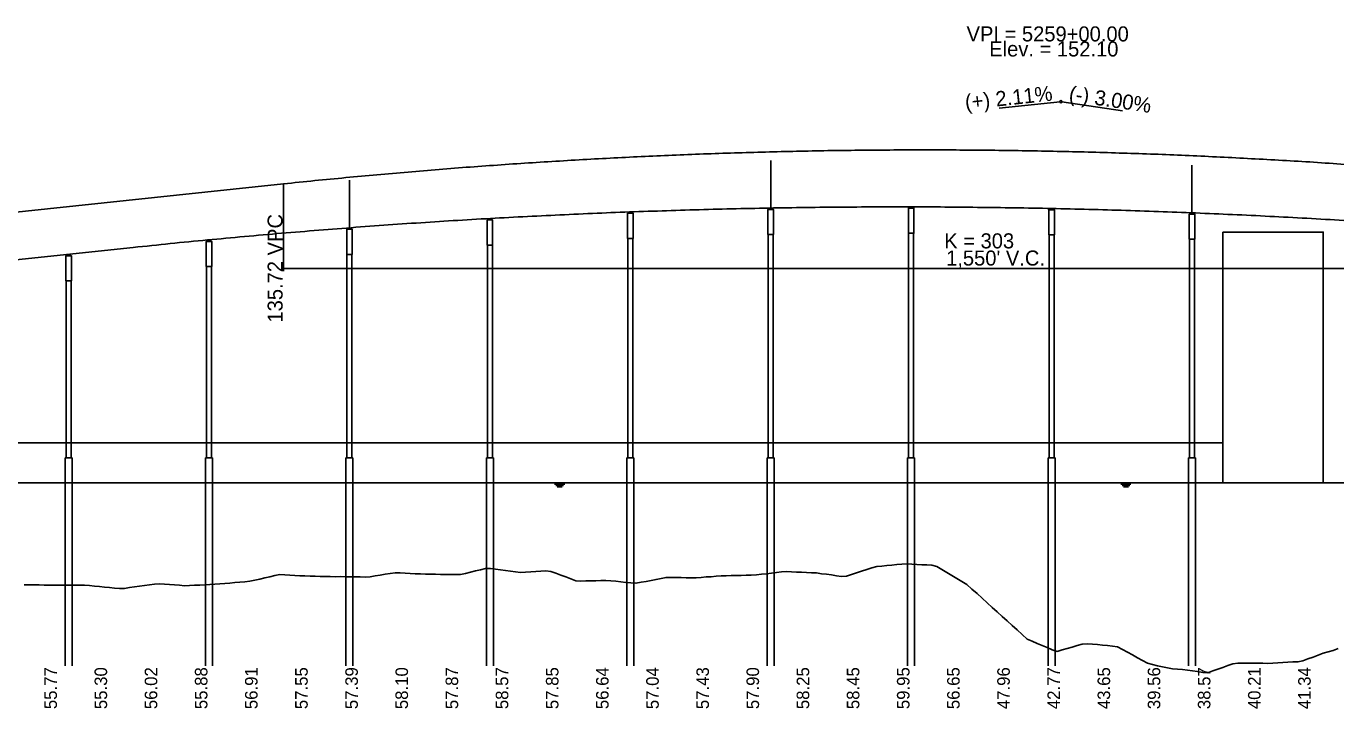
# Model space of a CAD drawing. Extents: x 2121671 to 2169879, y 557274 to 599957.
# Drawn here: x 2154437 to 2155742, y 595763 to 596443 of the extents above; entities that cross this region are included whole.
import ezdxf

# ---------------------------------------------------------------- set-up
doc = ezdxf.new("R2010")
doc.units = 0
for name, color, linetype in [('BR_CONCRETE', 7, 'Continuous'), ('BR_DETAILS', 7, 'Continuous'), ('BR_PRESTRESSED BEAM', 7, 'Continuous'), ('RD_DDB_GradeTX', 7, 'Continuous'), ('RD_DDB_Profile_Elev', 7, 'Continuous'), ('RD_DDB_Profile_EX', 7, 'Continuous'), ('RD_DDB_Profile_Lbl', 7, 'Continuous'), ('RD_DDB_Profile_PR', 7, 'Continuous'), ('RD_DDB_StripGrade', 7, 'Continuous'), ('RD_DDB_VCLbl', 7, 'Continuous')]:
    doc.layers.add(name, color=color, linetype=linetype)

msp = doc.modelspace()

# ---------------------------------------------------------------- linework, layer by layer
at = {"layer": 'BR_CONCRETE'}
for p, q in [((2155176.3, 596235.7), (2155176.3, 596013.1)), ((2155181.3, 596235.7), (2155181.3, 596013.1)), ((2155316.3, 596236.9), (2155316.3, 596013.1)), ((2155321.3, 596236.9), (2155321.3, 596013.1)), ((2155456.3, 596235.3), (2155456.3, 596013.1)), ((2155461.3, 596235.3), (2155461.3, 596013.1)), ((2154896.3, 596225.1), (2154896.3, 596013.1)), ((2154901.3, 596225.1), (2154901.3, 596013.1)), ((2155036.3, 596231.8), (2155036.3, 596013.1)), ((2155041.3, 596231.8), (2155041.3, 596013.1)), ((2155596.3, 596231), (2155596.3, 596013.1)), ((2155601.3, 596231), (2155601.3, 596013.1)), ((2154756.3, 596215.8), (2154756.3, 596013.1)), ((2154761.3, 596215.8), (2154761.3, 596013.1)), ((2154616.3, 596203.8), (2154616.3, 596013.1)), ((2154621.3, 596203.8), (2154621.3, 596013.1)), ((2154476.3, 596189.4), (2154476.3, 596013.1)), ((2154481.3, 596189.4), (2154481.3, 596013.1)), ((2154475.3, 596013.1), (2154475.3, 595805.8)), ((2154482.3, 596013.1), (2154482.3, 595805.8)), ((2154615.3, 596013.1), (2154615.3, 595805.8)), ((2154622.3, 596013.1), (2154622.3, 595805.8)), ((2154755.3, 596013.1), (2154755.3, 595805.8)), ((2154762.3, 596013.1), (2154762.3, 595805.8)), ((2154895.3, 596013.1), (2154895.3, 595805.8)), ((2154902.3, 596013.1), (2154902.3, 595805.8)), ((2155035.3, 596013.1), (2155035.3, 595805.8)), ((2155042.3, 596013.1), (2155042.3, 595805.8)), ((2155175.3, 596013.1), (2155175.3, 595805.8)), ((2155182.3, 596013.1), (2155182.3, 595805.8)), ((2155315.3, 596013.1), (2155315.3, 595805.8)), ((2155322.3, 596013.1), (2155322.3, 595805.8)), ((2155455.3, 596013.1), (2155455.3, 595805.8)), ((2155462.3, 596013.1), (2155462.3, 595805.8)), ((2155595.3, 596013.1), (2155595.3, 595805.8)), ((2155602.3, 596013.1), (2155602.3, 595805.8))]:
    msp.add_line(p, q, dxfattribs=at)
for points in [[(2155176.1, 596235.7), (2155181.6, 596235.7), (2155181.6, 596260.7), (2155176.1, 596260.7)], [(2155316.1, 596236.9), (2155321.6, 596236.9), (2155321.6, 596261.9), (2155316.1, 596261.9)], [(2154896.1, 596225.1), (2154901.6, 596225.1), (2154901.6, 596250.1), (2154896.1, 596250.1)], [(2155036.1, 596231.8), (2155041.6, 596231.8), (2155041.6, 596256.8), (2155036.1, 596256.8)], [(2155456.1, 596235.3), (2155461.6, 596235.3), (2155461.6, 596260.3), (2155456.1, 596260.3)], [(2155596.1, 596231), (2155601.6, 596231), (2155601.6, 596256), (2155596.1, 596256)], [(2154756.1, 596215.8), (2154761.6, 596215.8), (2154761.6, 596240.8), (2154756.1, 596240.8)], [(2154616.1, 596203.8), (2154621.6, 596203.8), (2154621.6, 596228.8), (2154616.1, 596228.8)], [(2154476.1, 596189.4), (2154481.6, 596189.4), (2154481.6, 596214.4), (2154476.1, 596214.4)]]:
    msp.add_lwpolyline(points, close=True, dxfattribs=at)
at = {"layer": 'BR_DETAILS'}
for points in [[(2155177.3, 596261.9), (2155178.3, 596261.9), (2155178.3, 596260.7), (2155177.3, 596260.7)], [(2155179.3, 596261.9), (2155180.3, 596261.9), (2155180.3, 596260.7), (2155179.3, 596260.7)], [(2155317.3, 596263.1), (2155318.3, 596263.1), (2155318.3, 596261.9), (2155317.3, 596261.9)], [(2155319.3, 596263.1), (2155320.3, 596263.1), (2155320.3, 596261.9), (2155319.3, 596261.9)], [(2155457.3, 596261.5), (2155458.3, 596261.5), (2155458.3, 596260.3), (2155457.3, 596260.3)], [(2155459.3, 596261.5), (2155460.3, 596261.5), (2155460.3, 596260.3), (2155459.3, 596260.3)], [(2154897.3, 596251.4), (2154898.3, 596251.4), (2154898.3, 596250.1), (2154897.3, 596250.1)], [(2154899.3, 596251.4), (2154900.3, 596251.4), (2154900.3, 596250.1), (2154899.3, 596250.1)], [(2155037.3, 596258), (2155038.3, 596258), (2155038.3, 596256.8), (2155037.3, 596256.8)], [(2155039.3, 596258), (2155040.3, 596258), (2155040.3, 596256.8), (2155039.3, 596256.8)], [(2155597.3, 596257.3), (2155598.3, 596257.3), (2155598.3, 596256), (2155597.3, 596256)], [(2155599.3, 596257.3), (2155600.3, 596257.3), (2155600.3, 596256), (2155599.3, 596256)], [(2154757.3, 596242.1), (2154758.3, 596242.1), (2154758.3, 596240.8), (2154757.3, 596240.8)], [(2154759.3, 596242.1), (2154760.3, 596242.1), (2154760.3, 596240.8), (2154759.3, 596240.8)], [(2154617.3, 596230), (2154618.3, 596230), (2154618.3, 596228.8), (2154617.3, 596228.8)], [(2154619.3, 596230), (2154620.3, 596230), (2154620.3, 596228.8), (2154619.3, 596228.8)], [(2154477.3, 596215.6), (2154478.3, 596215.6), (2154478.3, 596214.4), (2154477.3, 596214.4)], [(2154479.3, 596215.6), (2154480.3, 596215.6), (2154480.3, 596214.4), (2154479.3, 596214.4)]]:
    msp.add_lwpolyline(points, close=True, dxfattribs=at)
at = {"layer": 'BR_PRESTRESSED BEAM'}
for p, q in [((2155178.8, 596261.9), (2155178.8, 596309.4)), ((2155598.8, 596257.3), (2155598.8, 596304.8)), ((2154758.8, 596242.2), (2154758.8, 596289.7)), ((2154250.2, 596191.8), (2154543.2, 596222.7)), ((2154475.3, 596013.1), (2154482.3, 596013.1)), ((2154615.3, 596013.1), (2154622.3, 596013.1)), ((2154755.3, 596013.1), (2154762.3, 596013.1)), ((2154895.3, 596013.1), (2154902.3, 596013.1)), ((2155035.3, 596013.1), (2155042.3, 596013.1)), ((2155175.3, 596013.1), (2155182.3, 596013.1)), ((2155315.3, 596013.1), (2155322.3, 596013.1)), ((2155455.3, 596013.1), (2155462.3, 596013.1)), ((2155595.3, 596013.1), (2155602.3, 596013.1))]:
    msp.add_line(p, q, dxfattribs=at)
msp.add_spline([(2154543.2, 596222.7), (2154580.2, 596226.6), (2154617.2, 596230.2), (2154654.2, 596233.6), (2154691.2, 596236.9), (2154728.2, 596239.9), (2154765.2, 596242.8), (2154802.2, 596245.5), (2154839.2, 596248), (2154876.2, 596250.3), (2154913.2, 596252.4), (2154950.2, 596254.3), (2154987.2, 596256), (2155024.2, 596257.6), (2155061.2, 596258.9), (2155098.2, 596260.1), (2155135.2, 596261.1), (2155172.2, 596261.9), (2155209.2, 596262.5), (2155246.2, 596262.9), (2155283.2, 596263.1), (2155320.2, 596263.1), (2155357.2, 596263), (2155394.2, 596262.6), (2155431.2, 596262.1), (2155468.2, 596261.3), (2155505.2, 596260.4), (2155542.2, 596259.3), (2155579.2, 596258), (2155616.2, 596256.5), (2155653.2, 596254.9), (2155690.2, 596253), (2155727.2, 596251), (2155764.2, 596248.7), (2155801.2, 596246.3), (2155838.2, 596243.7), (2155875.2, 596240.9), (2155912.2, 596237.9), (2155949.2, 596234.7), (2155986.2, 596231.3), (2156023.2, 596227.7), (2156060.2, 596224), (2156097.2, 596220.1), (2156134.2, 596215.9), (2156171.2, 596211.6), (2156208.2, 596207.1), (2156245.2, 596202.4), (2156282.2, 596197.5), (2156319.2, 596192.4), (2156356.2, 596187.2), (2156393.2, 596181.7)], degree=3, dxfattribs=at)
at = {"layer": 'RD_DDB_GradeTX'}
for p, q in [((2155406.6, 596361.4), (2155467.3, 596367.9)), ((2155529.6, 596358.8), (2155469.2, 596367.8))]:
    msp.add_line(p, q, dxfattribs=at)
msp.add_circle((2155468.2, 596368), 1, dxfattribs=at)
at = {"layer": 'RD_DDB_Profile_Elev'}
for p, q in [((2151940.7, 596028.1), (2155629.7, 596028.1)), ((2151972, 595988.1), (2156334.9, 595988.1)), ((2154963.4, 595986.8), (2154973.4, 595986.8)), ((2155528, 595986.8), (2155538, 595986.8)), ((2154964.7, 595985.6), (2154972.2, 595985.6)), ((2154965.9, 595984.3), (2154970.9, 595984.3)), ((2155529.3, 595985.6), (2155536.8, 595985.6)), ((2155530.5, 595984.3), (2155535.5, 595984.3))]:
    msp.add_line(p, q, dxfattribs=at)
msp.add_lwpolyline([(2155629.7, 596238.1), (2155729.7, 596238.1), (2155729.7, 595988.1), (2155629.7, 595988.1)], close=True, dxfattribs=at)
at = {"layer": 'RD_DDB_Profile_EX'}
for points in [[(2154434.5, 595886.7), (2154439.5, 595886.6), (2154444.5, 595886.6), (2154449.5, 595886.5), (2154454.5, 595886.4), (2154459.5, 595886.3), (2154464.5, 595886.3), (2154469.5, 595886.3), (2154474.5, 595886.3), (2154479.5, 595886.3), (2154484.5, 595886.3), (2154489.5, 595886.3), (2154494.5, 595886.3), (2154499.5, 595885.9), (2154504.5, 595885.4), (2154509.5, 595884.9), (2154514.5, 595884.3), (2154519.5, 595883.8), (2154524.5, 595883.3), (2154529.5, 595882.8), (2154534.5, 595883.1), (2154539.5, 595883.8), (2154544.5, 595884.5), (2154549.5, 595885.3), (2154554.5, 595886), (2154559.5, 595886.7), (2154564.5, 595887.4), (2154569.5, 595887.6), (2154574.5, 595887.2), (2154579.5, 595886.9), (2154584.5, 595886.5), (2154589.5, 595886.1), (2154594.5, 595885.7), (2154599.5, 595885.8), (2154604.5, 595886.1), (2154609.5, 595886.4), (2154614.5, 595886.7), (2154619.5, 595887), (2154624.5, 595887.2), (2154629.5, 595887.5), (2154634.5, 595887.9), (2154639.5, 595888.3), (2154644.5, 595888.8), (2154649.5, 595889.2), (2154654.5, 595889.7), (2154659.5, 595890.1), (2154664.5, 595891.2), (2154669.5, 595892.3), (2154674.5, 595893.5), (2154679.5, 595894.7), (2154684.5, 595895.8), (2154689.5, 595896.9), (2154694.5, 595896.6)], [(2154694.5, 595896.6), (2154699.5, 595896.3), (2154704.5, 595896), (2154709.5, 595895.7), (2154714.5, 595895.4), (2154719.5, 595895.2), (2154724.5, 595895.1), (2154729.5, 595895), (2154734.5, 595894.9), (2154739.5, 595894.8), (2154744.5, 595894.7), (2154749.5, 595894.8), (2154754.5, 595894.7), (2154759.5, 595894.6), (2154764.5, 595894.5), (2154769.5, 595894.4), (2154774.5, 595894.3), (2154779.5, 595894.7), (2154784.5, 595895.5), (2154789.5, 595896.3), (2154794.5, 595897.1), (2154799.5, 595897.9), (2154804.5, 595898.6), (2154809.5, 595898.4), (2154814.5, 595898.1), (2154819.5, 595897.9), (2154824.5, 595897.7), (2154829.5, 595897.4), (2154834.5, 595897.2), (2154839.5, 595897.2), (2154844.5, 595897.1), (2154849.5, 595897), (2154854.5, 595897), (2154859.5, 595896.9), (2154864.5, 595896.9), (2154869.5, 595896.8), (2154874.5, 595898), (2154879.5, 595899.3), (2154884.5, 595900.5), (2154889.5, 595901.7), (2154894.5, 595902.9), (2154899.5, 595902.9), (2154904.5, 595902.2), (2154909.5, 595901.5), (2154914.5, 595900.8), (2154919.5, 595900.2), (2154924.5, 595899.5), (2154929.5, 595899), (2154934.5, 595899.3), (2154939.5, 595899.6), (2154944.5, 595899.9), (2154949.5, 595900.2), (2154954.5, 595900.5), (2154959.5, 595900), (2154964.5, 595898.1), (2154969.5, 595896.3), (2154974.5, 595894.4), (2154979.5, 595892.6), (2154984.5, 595890.7), (2154989.5, 595890.4), (2154994.5, 595890.5), (2154999.5, 595890.6), (2155004.5, 595890.7), (2155009.5, 595890.8), (2155014.5, 595890.8), (2155019.5, 595890.6), (2155024.5, 595890.1), (2155029.5, 595889.6), (2155034.5, 595889), (2155039.5, 595888.5), (2155044.5, 595888.1), (2155049.5, 595889.1), (2155054.5, 595890), (2155059.5, 595891), (2155064.5, 595892), (2155069.5, 595892.9), (2155074.5, 595893.9), (2155079.5, 595893.9), (2155084.5, 595893.8), (2155089.5, 595893.8), (2155094.5, 595893.7), (2155099.5, 595893.7), (2155104.5, 595893.7), (2155109.5, 595894), (2155114.5, 595894.4), (2155119.5, 595894.7), (2155124.5, 595895.1), (2155129.5, 595895.4), (2155134.5, 595895.7), (2155139.5, 595895.8), (2155144.5, 595895.9), (2155149.5, 595896), (2155154.5, 595896.1), (2155159.5, 595896.2), (2155164.5, 595896.5), (2155169.5, 595897.1), (2155174.5, 595897.7), (2155179.5, 595898.3), (2155184.5, 595898.9), (2155189.5, 595899.5), (2155194.5, 595899.8)], [(2155194.5, 595899.8), (2155199.5, 595899.5), (2155204.5, 595899.3), (2155209.5, 595899.1), (2155214.5, 595898.9), (2155219.5, 595898.7), (2155224.5, 595898.4), (2155229.5, 595897.7), (2155234.5, 595897.1), (2155239.5, 595896.4), (2155244.5, 595895.7), (2155249.5, 595895), (2155254.5, 595895.1), (2155259.5, 595896.8), (2155264.5, 595898.5), (2155269.5, 595900.1), (2155274.5, 595901.8), (2155279.5, 595903.4), (2155284.5, 595904.7), (2155289.5, 595905.2), (2155294.5, 595905.7), (2155299.5, 595906.2), (2155304.5, 595906.7), (2155309.5, 595907.2), (2155314.5, 595907.4), (2155319.5, 595907.1), (2155324.5, 595906.9), (2155329.5, 595906.6), (2155334.5, 595906.4), (2155339.5, 595906.1), (2155344.5, 595905), (2155349.5, 595902), (2155354.5, 595899), (2155359.5, 595896), (2155364.5, 595893), (2155369.5, 595890), (2155374.5, 595887), (2155379.5, 595882.4), (2155384.5, 595877.8), (2155389.5, 595873.2), (2155394.5, 595868.6), (2155399.5, 595864), (2155404.5, 595859.6), (2155409.5, 595855.2), (2155414.5, 595850.7), (2155419.5, 595846.2), (2155424.5, 595841.7), (2155429.5, 595837.2), (2155434.5, 595832.6), (2155439.5, 595830.5), (2155444.5, 595828.3), (2155449.5, 595826.2), (2155454.5, 595824), (2155459.5, 595821.8), (2155464.5, 595820.2), (2155469.5, 595821.7), (2155474.5, 595823.1), (2155479.5, 595824.6), (2155484.5, 595826), (2155489.5, 595827.5), (2155494.5, 595827.9), (2155499.5, 595827.4), (2155504.5, 595827), (2155509.5, 595826.5), (2155514.5, 595826.1), (2155519.5, 595825.6), (2155524.5, 595824.8), (2155529.5, 595822.1), (2155534.5, 595819.4), (2155539.5, 595816.7), (2155544.5, 595813.9), (2155549.5, 595811.2), (2155554.5, 595808.4), (2155559.5, 595807.1), (2155564.5, 595806), (2155569.5, 595805), (2155574.5, 595804), (2155579.5, 595803), (2155584.5, 595802.5), (2155589.5, 595802.3), (2155594.5, 595801.6), (2155599.5, 595800.8), (2155604.5, 595800.1), (2155609.5, 595799.3), (2155614.5, 595799), (2155619.5, 595800.8), (2155624.5, 595802.5), (2155629.5, 595804.3), (2155634.5, 595806.1), (2155639.5, 595807.9), (2155644.5, 595808.5), (2155649.5, 595808.5), (2155654.5, 595808.5), (2155659.5, 595808.5), (2155664.5, 595808.5), (2155669.5, 595808.5), (2155674.5, 595808.3), (2155679.5, 595808.5), (2155684.5, 595808.9), (2155689.5, 595809.2), (2155694.5, 595809.6)], [(2155694.5, 595809.6), (2155699.5, 595810), (2155704.5, 595809.8), (2155709.5, 595810.9), (2155714.5, 595812.7), (2155719.5, 595814.6), (2155724.5, 595816.5), (2155729.5, 595818.4), (2155734.5, 595819.9), (2155739.5, 595821.3), (2155744.5, 595823.3)]]:
    msp.add_lwpolyline(points, dxfattribs=at)
at = {"layer": 'RD_DDB_Profile_PR'}
msp.add_line((2154250.2, 596239.3), (2154693.2, 596286.1), dxfattribs=at)
msp.add_spline([(2154693.2, 596286.1), (2154724.2, 596289.3), (2154755.2, 596292.3), (2154786.2, 596295.2), (2154817.2, 596297.9), (2154848.2, 596300.5), (2154879.2, 596302.9), (2154910.2, 596305.1), (2154941.2, 596307.2), (2154972.2, 596309.1), (2155003.2, 596310.9), (2155034.2, 596312.5), (2155065.2, 596314), (2155096.2, 596315.3), (2155127.2, 596316.4), (2155158.2, 596317.4), (2155189.2, 596318.2), (2155220.2, 596318.9), (2155251.2, 596319.4), (2155282.2, 596319.7), (2155313.2, 596319.9), (2155344.2, 596319.9), (2155375.2, 596319.8), (2155406.2, 596319.5), (2155437.2, 596319), (2155468.2, 596318.4), (2155499.2, 596317.7), (2155530.2, 596316.7), (2155561.2, 596315.7), (2155592.2, 596314.4), (2155623.2, 596313), (2155654.2, 596311.4), (2155685.2, 596309.7), (2155716.2, 596307.9), (2155747.2, 596305.8), (2155778.2, 596303.6), (2155809.2, 596301.3), (2155840.2, 596298.8), (2155871.2, 596296.1), (2155902.2, 596293.3), (2155933.2, 596290.3), (2155964.2, 596287.1), (2155995.2, 596283.8), (2156026.2, 596280.4), (2156057.2, 596276.8), (2156088.2, 596273), (2156119.2, 596269), (2156150.2, 596264.9), (2156181.2, 596260.7), (2156212.2, 596256.3), (2156243.2, 596251.7)], degree=3, dxfattribs=at)
at = {"layer": 'RD_DDB_VCLbl'}
for p, q in [((2154693.2, 596199.2), (2154693.2, 596286.1)), ((2154693.2, 596201.7), (2156243.2, 596201.7))]:
    msp.add_line(p, q, dxfattribs=at)

# ---------------------------------------------------------------- texts
at = {"layer": 'RD_DDB_GradeTX'}
for s, rotation, p in [('(+) 2.11%', 6.0299, (2155373.3, 596359.9)), ('(-) 3.00%', 351.4692, (2155475.5, 596368.9))]:
    msp.add_text(s, height=15, rotation=rotation, dxfattribs=at).set_placement(p)
at = {"layer": 'RD_DDB_Profile_Lbl'}
for s, p in [('VPI = 5259+00.00', (2155374.1, 596428)), ('Elev. = 152.10', (2155396.7, 596413))]:
    msp.add_text(s, height=15, dxfattribs=at).set_placement(p)
at = {"layer": 'RD_DDB_StripGrade'}
for s, height, p in [('135.72 VPC', 15, (2154692.2, 596147.9)), ('55.77', 12.5, (2154467.2, 595762.7)), ('55.30', 12.5, (2154517.2, 595762.7)), ('56.02', 12.5, (2154567.2, 595762.7)), ('55.88', 12.5, (2154617.2, 595762.7)), ('56.91', 12.5, (2154667.2, 595762.7)), ('57.55', 12.5, (2154717.2, 595762.7)), ('57.39', 12.5, (2154767.2, 595762.7)), ('58.10', 12.5, (2154817.2, 595762.7)), ('57.87', 12.5, (2154867.2, 595762.7)), ('58.57', 12.5, (2154917.2, 595762.7)), ('57.85', 12.5, (2154967.2, 595762.7)), ('56.64', 12.5, (2155017.2, 595762.7)), ('57.04', 12.5, (2155067.2, 595762.7)), ('57.43', 12.5, (2155117.2, 595762.7)), ('57.90', 12.5, (2155167.2, 595762.7)), ('58.25', 12.5, (2155217.2, 595762.7)), ('58.45', 12.5, (2155267.2, 595762.7)), ('59.95', 12.5, (2155317.2, 595762.7)), ('56.65', 12.5, (2155367.2, 595762.7)), ('47.96', 12.5, (2155417.2, 595762.7)), ('42.77', 12.5, (2155467.2, 595762.7)), ('43.65', 12.5, (2155517.2, 595762.7)), ('39.56', 12.5, (2155567.2, 595762.7)), ('38.57', 12.5, (2155617.2, 595762.7)), ('40.21', 12.5, (2155667.2, 595762.7)), ('41.34', 12.5, (2155717.2, 595762.7))]:
    msp.add_text(s, height=height, rotation=90, dxfattribs=at).set_placement(p)
at = {"layer": 'RD_DDB_VCLbl'}
for s, p in [('K = 303', (2155351.8, 596221.8)), ("1,550' V.C.", (2155353.7, 596204.7))]:
    msp.add_text(s, height=15, dxfattribs=at).set_placement(p)

doc.saveas('drawing.dxf')
